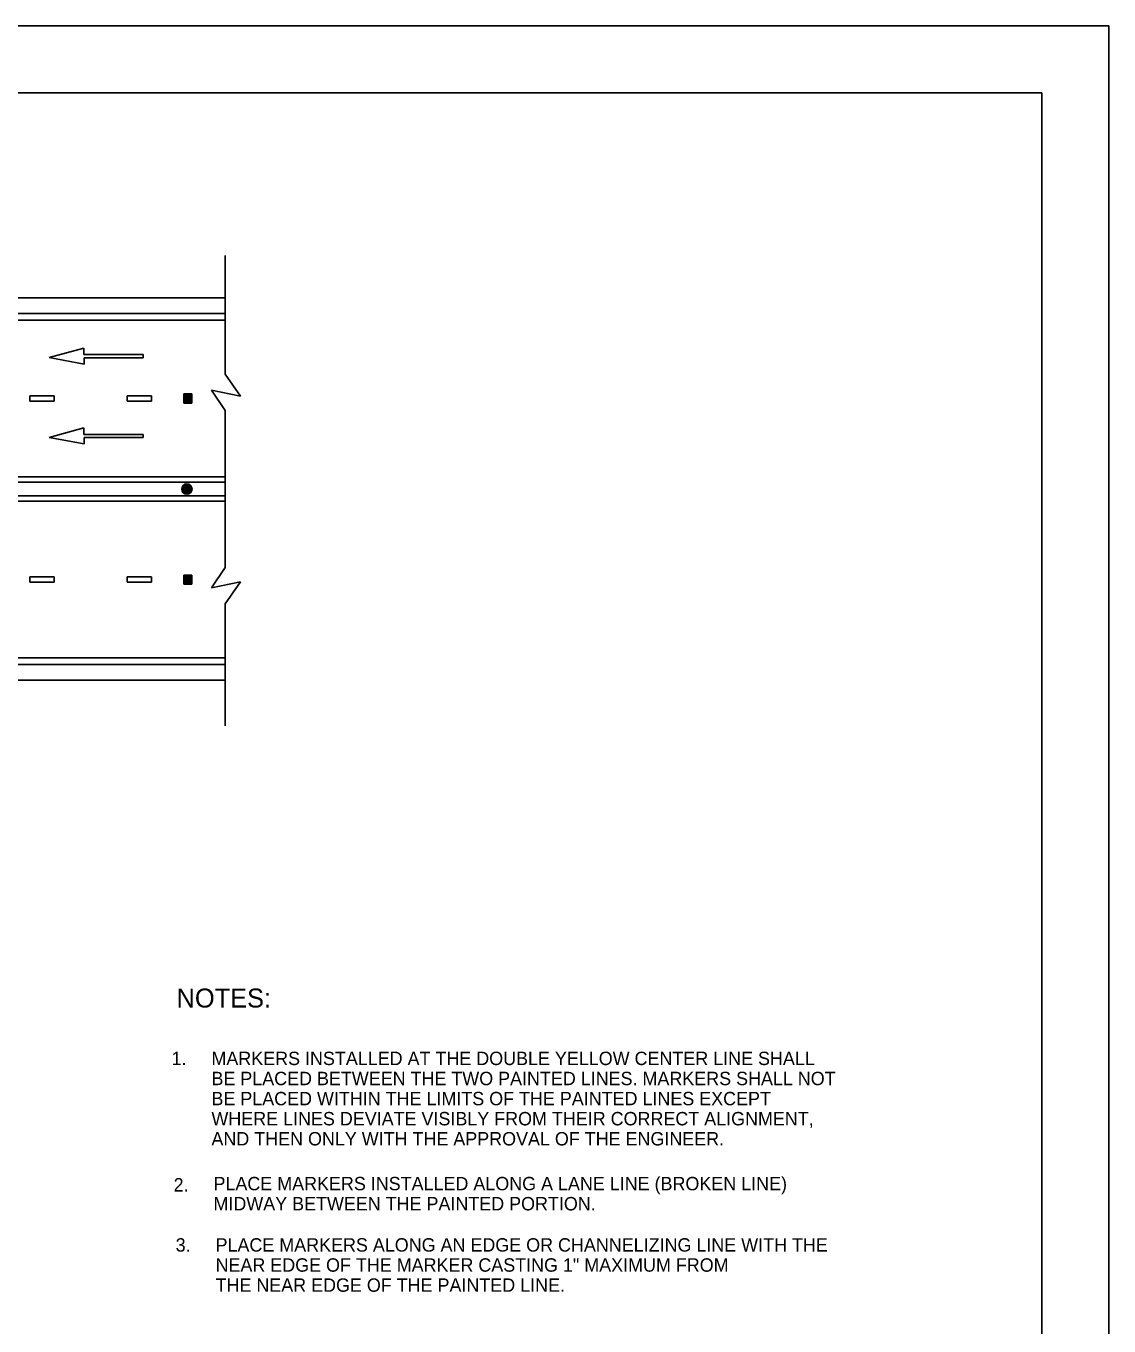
# Model space of a CAD drawing. Extents: x 639362 to 641108, y 298458 to 299646.
# Drawn here: x 640801.8 to 641044.3, y 299354.5 to 299645.6 of the extents above; entities that cross this region are included whole.
import ezdxf

# ---------------------------------------------------------------- set-up
doc = ezdxf.new("R2010")
doc.units = 0
for name, color, linetype in [('1', 7, 'Continuous'), ('2', 7, 'Continuous'), ('PLT-BNDY', 7, 'Continuous')]:
    doc.layers.add(name, color=color, linetype=linetype)

msp = doc.modelspace()

# ---------------------------------------------------------------- linework, layer by layer
at = {"layer": '1'}
for p in [(640243.31, 299630.63), (641029.31, 299066.63)]:
    msp.add_line(p, (641029.31, 299630.63), dxfattribs=at)
at = {"layer": '2'}
for p, q in [((640846.38, 299594.26), (640846.38, 299567.63)), ((640568.94, 299584.74), (640846.38, 299584.74)), ((640568.94, 299581.24), (640846.38, 299581.24)), ((640568.94, 299579.74), (640846.38, 299579.74)), ((640814.73, 299573.5), (640807.01, 299571.38)), ((640814.73, 299572.06), (640814.73, 299573.5)), ((640807.01, 299571.38), (640814.81, 299569.91)), ((640828.06, 299572.06), (640814.73, 299572.06)), ((640814.81, 299569.91), (640814.81, 299571.35)), ((640814.81, 299571.35), (640828.06, 299571.35)), ((640828.06, 299571.35), (640828.06, 299572.06)), ((640849.87, 299562.73), (640846.38, 299567.63)), ((640808.14, 299562.81), (640802.7, 299562.81)), ((640802.7, 299562.81), (640802.7, 299561.61)), ((640802.7, 299561.61), (640808.14, 299561.61)), ((640808.14, 299561.61), (640808.14, 299562.81)), ((640824.45, 299561.61), (640824.45, 299562.81)), ((640824.45, 299562.81), (640829.89, 299562.81)), ((640829.89, 299561.61), (640824.45, 299561.61)), ((640829.89, 299562.81), (640829.89, 299561.61)), ((640837.16, 299563.23), (640838.93, 299563.23)), ((640837.16, 299561.19), (640837.16, 299563.23)), ((640837.33, 299563.05), (640838.75, 299563.05)), ((640837.33, 299561.36), (640837.33, 299563.05)), ((640838.75, 299561.36), (640837.33, 299561.36)), ((640837.51, 299562.87), (640838.58, 299562.87)), ((640837.51, 299561.54), (640837.51, 299562.87)), ((640838.58, 299561.54), (640837.51, 299561.54)), ((640837.69, 299561.72), (640837.69, 299562.69)), ((640837.69, 299562.69), (640838.4, 299562.69)), ((640838.4, 299561.72), (640837.69, 299561.72)), ((640837.87, 299562.52), (640838.22, 299562.52)), ((640837.87, 299561.9), (640837.87, 299562.52)), ((640838.22, 299561.9), (640837.87, 299561.9)), ((640838.04, 299562.34), (640838.04, 299562.07)), ((640838.22, 299562.52), (640838.22, 299561.9)), ((640838.4, 299562.69), (640838.4, 299561.72)), ((640838.58, 299562.87), (640838.58, 299561.54)), ((640838.75, 299563.05), (640838.75, 299561.36)), ((640838.93, 299563.23), (640838.93, 299561.19)), ((640846.38, 299559.5), (640843.33, 299564.08)), ((640843.33, 299564.08), (640849.87, 299562.73)), ((640838.93, 299561.19), (640837.16, 299561.19)), ((640846.38, 299524.36), (640846.38, 299559.5)), ((640814.73, 299555.62), (640807.01, 299553.51)), ((640814.73, 299554.18), (640814.73, 299555.62)), ((640807.01, 299553.51), (640814.81, 299552.03)), ((640828.06, 299554.18), (640814.73, 299554.18)), ((640814.81, 299552.03), (640814.81, 299553.47)), ((640814.81, 299553.47), (640828.06, 299553.47)), ((640828.06, 299553.47), (640828.06, 299554.18)), ((640846.38, 299544.68), (640568.94, 299544.68)), ((640846.38, 299543.48), (640846.38, 299544.68)), ((640568.94, 299543.48), (640846.38, 299543.48)), ((640846.38, 299540.38), (640568.94, 299540.38)), ((640568.94, 299539.18), (640846.38, 299539.18)), ((640846.38, 299539.18), (640846.38, 299540.38)), ((640846.38, 299524.36), (640843.33, 299519.78)), ((640808.14, 299522.25), (640802.7, 299522.25)), ((640802.7, 299522.25), (640802.7, 299521.05)), ((640802.7, 299521.05), (640808.14, 299521.05)), ((640808.14, 299521.05), (640808.14, 299522.25)), ((640824.45, 299521.05), (640824.45, 299522.25)), ((640824.45, 299522.25), (640829.89, 299522.25)), ((640829.89, 299521.05), (640824.45, 299521.05)), ((640829.89, 299522.25), (640829.89, 299521.05)), ((640837.16, 299522.67), (640838.93, 299522.67)), ((640837.16, 299520.63), (640837.16, 299522.67)), ((640838.93, 299520.63), (640837.16, 299520.63)), ((640837.33, 299522.49), (640838.75, 299522.49)), ((640837.33, 299520.81), (640837.33, 299522.49)), ((640838.75, 299520.81), (640837.33, 299520.81)), ((640837.51, 299522.31), (640838.58, 299522.31)), ((640837.51, 299520.98), (640837.51, 299522.31)), ((640838.58, 299520.98), (640837.51, 299520.98)), ((640837.69, 299521.16), (640837.69, 299522.14)), ((640837.69, 299522.14), (640838.4, 299522.14)), ((640838.4, 299521.16), (640837.69, 299521.16)), ((640837.87, 299521.96), (640838.22, 299521.96)), ((640837.87, 299521.34), (640837.87, 299521.96)), ((640838.22, 299521.34), (640837.87, 299521.34)), ((640838.04, 299521.78), (640838.04, 299521.51)), ((640838.22, 299521.96), (640838.22, 299521.34)), ((640838.4, 299522.14), (640838.4, 299521.16)), ((640838.58, 299522.31), (640838.58, 299520.98)), ((640838.75, 299522.49), (640838.75, 299520.81)), ((640838.93, 299522.67), (640838.93, 299520.63)), ((640843.33, 299519.78), (640849.87, 299521.13)), ((640849.87, 299521.13), (640846.38, 299516.24)), ((640846.38, 299488.88), (640846.38, 299516.24)), ((640568.94, 299504.12), (640846.38, 299504.12)), ((640568.94, 299502.62), (640846.38, 299502.62)), ((640568.94, 299499.12), (640846.38, 299499.12))]:
    msp.add_line(p, q, dxfattribs=at)
for radius in [1.15, 1.07, 0.985, 0.904, 0.822, 0.741, 0.659, 0.578, 0.496, 0.414, 0.333, 0.251, 0.17, 0.0881]:
    msp.add_circle((640837.85, 299541.93), radius, dxfattribs=at)
at = {"layer": 'PLT-BNDY'}
msp.add_lwpolyline([(640203.31, 299645.63), (641044.31, 299645.63), (641044.31, 299051.63), (640203.31, 299051.63)], close=True, dxfattribs=at)

# ---------------------------------------------------------------- texts
at = {"layer": '2'}
for s, height, p in [('NOTES:', 4.25, (640835.53, 299425.82)), ('1. ', 3, (640834.41, 299412.93)), ('MARKERS INSTALLED AT THE DOUBLE YELLOW CENTER LINE SHALL', 3, (640843.34, 299412.93)), ('BE PLACED BETWEEN THE TWO PAINTED LINES. MARKERS SHALL NOT', 3, (640843.34, 299408.43)), ('BE PLACED WITHIN THE LIMITS OF THE PAINTED LINES EXCEPT', 3, (640843.34, 299403.93)), ('WHERE LINES DEVIATE VISIBLY FROM THEIR CORRECT ALIGNMENT,', 3, (640843.34, 299399.43)), ('AND THEN ONLY WITH THE APPROVAL OF THE ENGINEER.', 3, (640843.34, 299394.93)), ('2. ', 3, (640834.87, 299384.61)), ('PLACE MARKERS INSTALLED ALONG A LANE LINE (BROKEN LINE)', 3, (640843.8, 299384.89)), ('MIDWAY BETWEEN THE PAINTED PORTION.', 3, (640843.8, 299380.39)), ('3. ', 3, (640835.33, 299371.16)), ('PLACE MARKERS ALONG AN EDGE OR CHANNELIZING LINE WITH THE', 3, (640844.26, 299371.16)), ('NEAR EDGE OF THE MARKER CASTING 1" MAXIMUM FROM ', 3, (640844.26, 299366.66)), ('THE NEAR EDGE OF THE PAINTED LINE.', 3, (640844.26, 299362.16))]:
    msp.add_text(s, height=height, dxfattribs=at).set_placement(p)

doc.saveas('drawing.dxf')
